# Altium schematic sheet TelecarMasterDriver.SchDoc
size 190 x 120 mm; PageSetup: Record=PageOptions?CenterHorizontal=True?CenterVertical=True?PrintScale=0.67?XCorrection=1.00?YCorrection=1.00?PrintKind=1?BorderSize=5000000?LeftOffset=0?BottomOffset=0?Orientation=2?PaperLength=1000?PaperWidth=1000?Scale=100?PaperSource=7?PrintQuality=-4?MediaType=1?DitherType=10?PaperKind=A5?PrintScaleMode=1
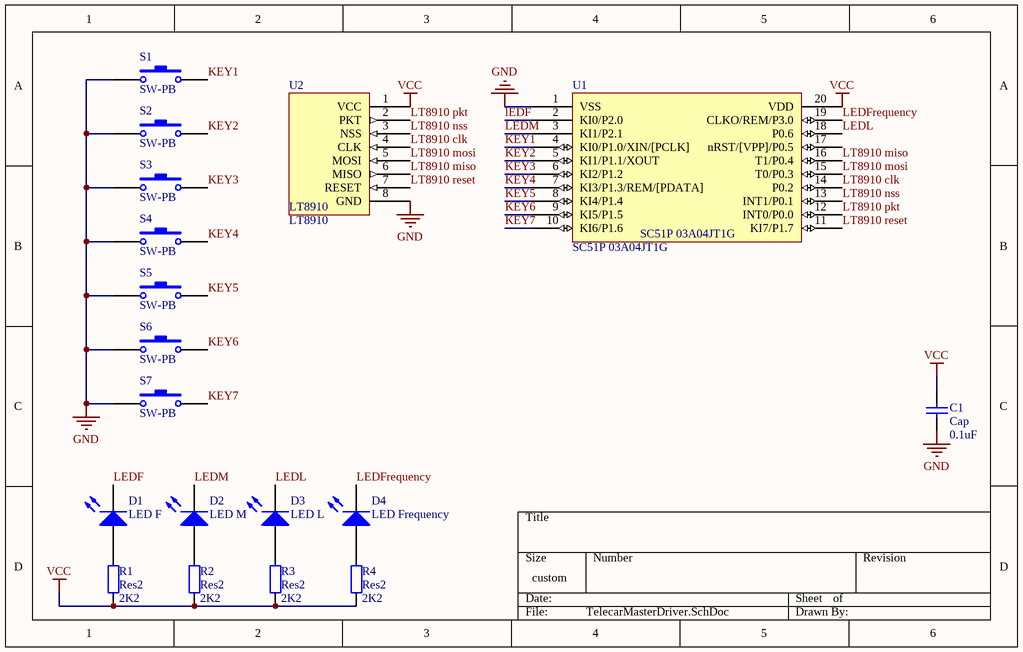
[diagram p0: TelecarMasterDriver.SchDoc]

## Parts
C1  Cap  value 0.1uF  [RAD-0.3]
D1  LED F  [LED-1]
D2  LED M  [LED-1]
D3  LED L  [LED-1]
D4  LED Frequency  [LED-1]
R1  Res2  value 2K2  [AXIAL-0.4]
R2  Res2  value 2K2  [AXIAL-0.4]
R3  Res2  value 2K2  [AXIAL-0.4]
R4  Res2  value 2K2  [AXIAL-0.4]
S1  SW-PB  [SPST-2]
S2  SW-PB  [SPST-2]
S3  SW-PB  [SPST-2]
S4  SW-PB  [SPST-2]
S5  SW-PB  [SPST-2]
S6  SW-PB  [SPST-2]
S7  SW-PB  [SPST-2]
U1  SC51P 03A04JT1G
U2  LT8910

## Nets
GND: C1.1 S1.1 S2.1 S3.1 S4.1 S5.1 S6.1 S7.1 U1.1(VSS) U2.8(GND)
VCC: C1.2 R1.1 R2.1 R3.1 R4.1 U1.20(VDD) U2.1(VCC)
KEY1: S1.2 U1.4(KI0/P1.0/XIN/[PCLK])
KEY2: S2.2 U1.5(KI1/P1.1/XOUT)
KEY3: S3.2 U1.6(KI2/P1.2)
KEY4: S4.2 U1.7(KI3/P1.3/REM/[PDATA])
KEY5: S5.2 U1.8(KI4/P1.4)
KEY6: S6.2 U1.9(KI5/P1.5)
KEY7: S7.2 U1.10(KI6/P1.6)
LEDF: D1.2(K) U1.2(KI0/P2.0)
LEDFrequency: D4.2(K) U1.19(CLKO/REM/P3.0)
LEDL: D3.2(K) U1.18(P0.6)
LEDM: D2.2(K) U1.3(KI1/P2.1)
LT8910 clk: U1.14(P0.2) U2.4(CLK)
LT8910 miso: U1.16(T1/P0.4) U2.6(MISO)
LT8910 mosi: U1.15(T0/P0.3) U2.5(MOSI)
LT8910 nss: U1.13(INT1/P0.1) U2.3(NSS)
LT8910 pkt: U1.12(INT0/P0.0) U2.2(PKT)
LT8910 reset: U1.11(KI7/P1.7) U2.7(RESET)
NetD1_1: D1.1(A) R1.2
NetD2_1: D2.1(A) R2.2
NetD3_1: D3.1(A) R3.2
NetD4_1: D4.1(A) R4.2

Not connected (* = marked no-connect by the designer): U1 17(nRST/[VPP]/P0.5)

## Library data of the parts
C1 = Cap: Capacitor
D1-D4 = LED1: Typical RED GaAs LED
R1-R4 = Res2: Resistor
S1-S7 = SW-PB: Switch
